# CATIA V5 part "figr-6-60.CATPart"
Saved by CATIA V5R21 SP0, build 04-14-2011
Part number: Part1
Bounding box of the stored display mesh (mm): x -50.648 to 50.648, y -72.183 to 72.183, z -40 to 40
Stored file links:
  D:\CATIA V5R21 E-RESOURCES\CATIA-V5R21\catia-v5r21-prt\c06-catia-v5r21-prt\c06-catia-v5r21-figr-6-60.CATPart
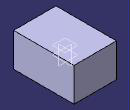
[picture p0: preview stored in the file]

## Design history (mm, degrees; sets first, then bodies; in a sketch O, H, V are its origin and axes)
Set1
  Plane1: type Offset, RefPlane xy-plane, Offset 20
Body1 (main body)
  Sketch1 on xy-plane, origin (0, 0, 0), H (1, 0, 0), V (0, 1, 0)
    line L1 (-50.6478, 72.1832) -> (50.6478, 72.1832)
    line L2 (50.6478, 72.1832) -> (50.6478, -72.1832)
    line L3 (50.6478, -72.1832) -> (-50.6478, -72.1832)
    line L4 (-50.6478, -72.1832) -> (-50.6478, 72.1832)
    axis line L5 (50.6478, -72.1832) -> (-50.6478, 72.1832)
    horizontal: L1 H, L3 H
    vertical: L2 V, L4 V
    midpoint: O L5
  Pad1: profile Sketch1, direction (0, 0, 1), length 40, mirrored extent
